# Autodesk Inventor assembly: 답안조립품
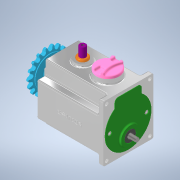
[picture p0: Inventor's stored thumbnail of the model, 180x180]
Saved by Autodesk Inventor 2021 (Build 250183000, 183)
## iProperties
Created: 2022-08
Part Number: 답안조립품
Document SubType Name: Assembly
Designer: Owner
Author: Owner
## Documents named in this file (16)
- C:\Users\Owner\Desktop\720810V1013\답안조립품.iam
- C:\Users\Owner\Desktop\720810V1013\본체.ipt
- C:\Users\Owner\Desktop\720810V1013\멈춤나사 M3.ipt
- C:\Users\Owner\Desktop\720810V1013\메인 축.ipt
- C:\Users\Owner\Desktop\720810V1013\베어링 608.ipt
- C:\Users\Owner\Desktop\720810V1013\베어링 6003.ipt
- C:\Users\Owner\Desktop\720810V1013\볼트 M4 x 10.ipt
- C:\Users\Owner\Desktop\720810V1013\부시.ipt
- C:\Users\Owner\Desktop\720810V1013\상부 캡.ipt
- C:\Users\Owner\Desktop\720810V1013\서브 축.ipt
- C:\Users\Owner\Desktop\720810V1013\스프로킷.ipt
- C:\Users\Owner\Desktop\720810V1013\슬라이더.ipt
- C:\Users\Owner\Desktop\720810V1013\오일 실 8 x 22 x 7.ipt
- C:\Users\Owner\Desktop\720810V1013\오일 실 17 x 32 x 8.ipt
- C:\Users\Owner\Desktop\720810V1013\커버.ipt
- C:\Users\Owner\Desktop\720810V1013\키 5 x 5.ipt
